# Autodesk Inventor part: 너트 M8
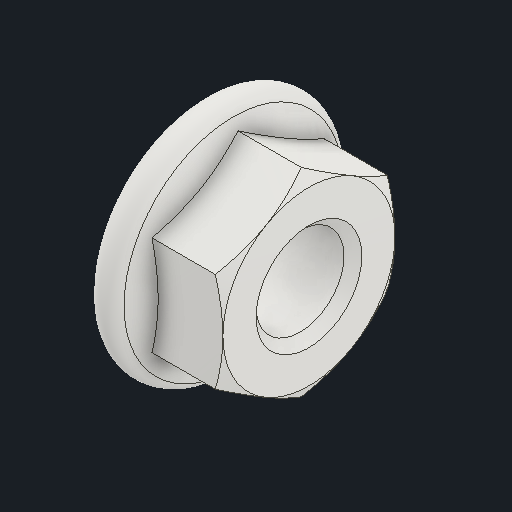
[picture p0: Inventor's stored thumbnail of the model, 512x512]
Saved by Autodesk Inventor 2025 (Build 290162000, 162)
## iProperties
Created: 2025-08
Part Number: 너트 M8
Material: 스테인리스강
Description: 플랜지붙이 6각 너트 - 일반 스레드
Document SubType Name: Modeling
Designer: infra023
Density: 8 g/cm^3
Appearance: 기본값
Author: jhkim
Sending System: Autodesk Inventor 2026
Preprocessor: ST-DEVELOPER v20.1
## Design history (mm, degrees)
feature "Solid1"
node "솔리드1"
